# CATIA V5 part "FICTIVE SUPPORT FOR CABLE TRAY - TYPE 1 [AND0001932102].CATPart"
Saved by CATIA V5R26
Part number: FICT-DS-00001
Description: FICTIVE SUPPORT FOR CABLE TRAY - TYPE 1
Publications: "EHISUPPORT-RefPoint1", "EHISUPPORT-RefPlane1.1", "EHISUPPORT-RefPlane2", "EHISUPPORT-RefBasePlane.1", "Absolute Axis System", "xy plane", "yz plane", "zx plane", "PartBody"
Bounding box of the stored display mesh (mm): x 0 to 20, y 0 to 10, z 0 to 2
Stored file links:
  \Lib_ELEC\FICTIVE SUPPORT FOR CABLE TRAY - TYPE 1 [AND0001932102].CATPart
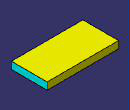
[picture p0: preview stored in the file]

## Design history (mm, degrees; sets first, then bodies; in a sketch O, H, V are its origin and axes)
AxisSystem1: origin (0, 0, 0), X (1, 0, 0), Y (0, 1, 0), Z (0, 0, 1)
Set1
  Point1: (10, 0, 10), in AxisSystem1
  Plane1: type Tangent, Support face of Pad1 from Sketch1.L4, RefPoint Point1
  Plane2: type Offset, RefPlane face of Pad1 from Sketch1.L2, Offset 0, reversed
  Plane3: type Offset, RefPlane end face of Pad1, Offset 0
Body1 (main body)
  Sketch1 on XY plane of AxisSystem1, origin (0, 0, 0), H (1, 0, 0), V (0, 1, 0)
    line L1 (20, 0) -> (20, 10)
    line L2 (20, 10) -> (0, 10)
    line L3 (0, 10) -> (0, 0)
    line L4 (0, 0) -> (20, 0)
    distance L1 L3 = 20
    distance L2 L4 = 10
    horizontal: L2 H, L4 H
    vertical: L1 V, L3 V
    coincidence: L4 H, L3 V
  Pad1: profile Sketch1, direction (0, 0, 1), length 2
